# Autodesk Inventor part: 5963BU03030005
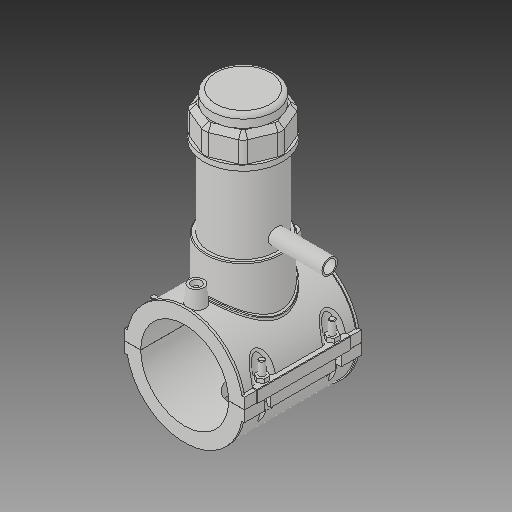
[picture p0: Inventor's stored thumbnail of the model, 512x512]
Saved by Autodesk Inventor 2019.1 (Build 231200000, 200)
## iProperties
Created: 2017-07
Part Number: 5963BU03030005
Material: Generic
Description: PLASSON TAPPING SADDLE 3''IPS x 1 1/2''CTS
Document SubType Name: Modeling
Designer: KIM
Mass: 1712.7 g
Surface Area: 2671.49 cm^2
Volume: 1712.7 cm^3
Density: 1 g/cm^3
Appearance: Default
Author: KIM
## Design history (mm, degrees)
derived "5963B.ipt"
feature "Solid1::5963B.ipt"
feature "Solid2::5963B.ipt"
feature "Solid4::5963B.ipt"
feature "Solid5::5963B.ipt"
tag "TaggingFeature1"
body "Solid1"
body "Solid2"
other parameters: "d0" = 88.7, "d2" = 120.904, "d3" = 22.175, "d4" = 118.11, "d5" = 0, "d6" = 0.1, "d8" = 0, "d19" = 6, "d20" = 6, "d21" = 70.866, "d23" = 0, "d24" = 35.433, "d26" = 0, "d29" = 3, "d30" = 29.56667, "d31" = 6, "d32" = 0, "d33" = 0, "d34" = 0.6, "d40" = 59.9612, "d41" = 79.83, "d43" = 0, "d45" = 0, "d47" = 128.521, "d70" = 15, "d72" = 0, "d73" = 6, "d75" = 5, "d76" = 0, "d77" = 4.435, "d78" = 74.35, "d79" = 15, "d80" = 47.244, "d82" = 5 deg, "d84" = 4, "d85" = 14, "d86" = 0, "d87" = 3, "d88" = 0, "d89" = 1, "d90" = 1, "d91" = 94.488, "d92" = 0, "d93" = 0.5, "d94" = 46.68421, "d96" = 117.6162, "d97" = 2.3622, "d98" = 0, "d102" = 0.887, "d120" = 140 deg, "d121" = 24.228, "d122" = 20 deg, "d123" = 230.62, "d124" = 69.186, "d126" = 0, "d143" = 91.361, "d145" = 20.46923, "d149" = 1.3305, "d150" = 22.51615, "d153" = 118.11, "d154" = 0, "d156" = 57.655, "d157" = 160 deg, "d159" = 5.322, "d161" = 1.3305, "d162" = 70.866, "d163" = 0, "d164" = 44.35, "d167" = 8.87, "d168" = 56.24878, "d170" = 3.2805, "d172" = 0, "d173" = 1, "d175" = 44.35, "d176" = 20 deg, "d177" = 6.209, "d178" = 26.61, "d180" = 0, "d183" = 10.644, "d184" = 4.9672, "d185" = 38.38575, "d186" = 38.38575, "d187" = 57.655, "d188" = 7.983, "d189" = 6.209, "d190" = 0, "d191" = 86.4825, "d193" = 6.1236, "d194" = 4.13385, "d195" = 90 deg, "d197" = 0, "d199" = 0, "d200" = 13.305, "d202" = 0, "d203" = 177.038, "d204" = 75.8385, "d205" = 55.881, "d206" = 67.8555, "d207" = 132.7785, "d208" = 138.08964, "d209" = 164.64534, "d210" = 68.6538, "d211" = 79.83, "d212" = 63.864, "d213" = 51.4116, "d216" = 0, "d217" = 8.87, "d218" = 4.435, "d219" = 0.887, "d222" = 88.7, "d224" = 0, "d230" = 5.322, "d233" = 6, "d236" = 60.452, "d237" = 35.433, "d238" = 6.02433, "d240" = 35.433, "d241" = 35.433, "d242" = 35.433, "d243" = 6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
